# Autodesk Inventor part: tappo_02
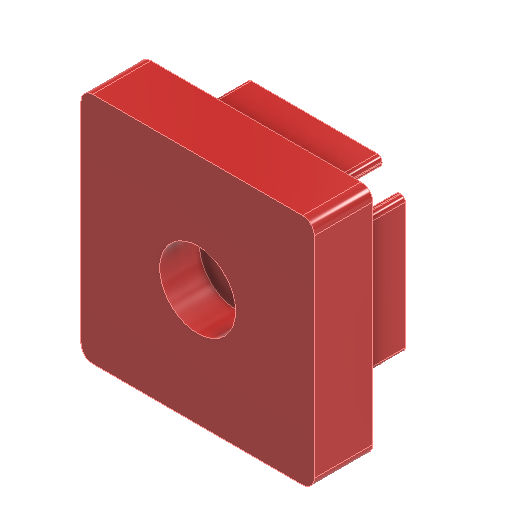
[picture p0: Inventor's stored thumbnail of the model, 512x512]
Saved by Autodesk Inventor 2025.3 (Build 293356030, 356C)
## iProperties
Created: 2026-02
Part Number: tappo_02
Material: Generico
Document SubType Name: Modeling
Designer: R5800u
Density: 1 g/cm^3
Appearance: Rosso arancio
Author: R5800u
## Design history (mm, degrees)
sketch "Schizzo1"
  geometry: L1 (10, 10)-(-10, 10); L2 (-10, 10)-(-10, -10); L3 (-10, -10)-(10, -10); L4 (10, -10)-(10, 10); L5 (10, 10)-(-10, -10); L6 (-10, 10)-(10, -10); L7 (6, -8)-(3, -8) reference; L8 (6, -7.061)-(6, -8) reference; L9 (2.939, -4)-(6, -7.061) reference; L10 (0, 0)-(0, -10); L11 (2.939, -4)-(0, -4); L12 (3, -8)-(0, -8); L13 (0, -7.8)-(3, -7.8); L14 (3, -7.8)-(5.8, -7.8); L15 (5.8, -7.8)-(5.8, -7.144); L16 (5.8, -7.144)-(2.856, -4.2); L17 (2.856, -4.2)-(0, -4.2); L18 (0, -7.8)-(-3, -7.8); L19 (-3, -7.8)-(-5.8, -7.8); L20 (-5.8, -7.8)-(-5.8, -7.144); L21 (-5.8, -7.144)-(-2.856, -4.2); L22 (-2.856, -4.2)-(0, -4.2)
  constraints: 38 end point, 4 symmetric about line, 3 midpoint, 3 perpendicular, 2 parallel, 2 point on line, 1 horizontal, 4 other
  dimensions: "d0" = 20 distance of L3.end L2.end; "d1" = 20 distance of L2.end L1.end; "d2" = 0.2 distance between parallel lines of L12 L13
  node "Riferimento1"
  node "Riferimento2"
  node "Riferimento3"
extrude "Estrusione1" new body sketch "Schizzo1" distance "d3" = 5; taper "d4" = 0 deg
extrude "Estrusione2" new body sketch "Schizzo1" distance "d5" = 1.9; taper "d6" = 0 deg; dims "d11" = 5, "d12" = 0
pattern_circular "Serie circolare1" dims angle "d8" = 360 deg
fillet "Raccordo2" dims "d13" = 0.4
fillet "Raccordo1" dims "d10" = 1
sketch "Schizzo2"
  geometry: 1 further point
hole "Foro1" sketch "Schizzo2" at (0, 0) diameter "d14" = 3.2; stored, may be unused: countersink angle "d18" = 90 deg, drill point angle "d20" = 118 deg; dims "d15" = 6, "d16" = 6.5, "d17" = 3.4, "d19" = 8
node "Solido1"
node "Solido2"
